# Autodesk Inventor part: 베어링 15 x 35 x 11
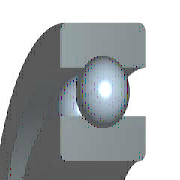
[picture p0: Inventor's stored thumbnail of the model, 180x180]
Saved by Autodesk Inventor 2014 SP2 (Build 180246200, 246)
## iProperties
Created: 2012-02
Part Number: 베어링 15 x 35 x 11
Material: 강철, 연강
Description: 깊은 그루브 볼 베어링
Document SubType Name: Modeling
Standard: KS B 2023
Designer: mduedu
Standards Organization: KS
Language: ko-KR
Size Designation: 6202 - 15 x 35 x 11
Categories: <MemberInstance><Categories><Category DisplayName="샤프트 부품" InternalName="7f7aeb1f-a693-4053-b835-cee3144e0d98" Mnemonic="SHFT"><Category DisplayName="베어링" Inter
Density: 1 g/cm^3
Appearance: 강철
IsCustomPart: 1
Author: mduedu
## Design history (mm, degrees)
sketch "스케치" dims "d0" = 5.2 (= -0.26 x WD + 0.26 x BD)
  geometry: L1 (2.9, 12.5)-(8.1, 12.5); L2 (5.5, 12.5)-(5.5, 9.9); L3 (5.5, 12.5)-(5.5, 15.1); L4 (3.568, 10.76)-(0, 10.76); L5 (0, 7.5)-(11, 7.5); L6 (3.568, 14.24)-(0, 14.24); L7 (0, 17.5)-(11, 17.5); L8 (11, 7.5)-(11, 10.76); L9 (7.432, 10.76)-(11, 10.76); L10 (7.432, 14.24)-(11, 14.24); L11 (11, 17.5)-(11, 14.24); L12 (-1.4, 0)-(8.4, 0) reference; L13 (0, -0.3)-(0, 5.3) reference
  constraints: 22 end point, 4 point on line, 2 collinear, 2 perpendicular, 2 symmetric about line, 1 midpoint, 1 parallel, 14 other
  dimensions: "d9" = 15 diameter of L5 L12 (= WD); "d11" = 35 diameter of L7 L12 (= BD); "d12" = 11 distance between parallel lines of L8 L13 (= KB); "d13" = 21.52 diameter of L9 L12 (= 0.326 x BD + 0.674 x WD)
revolve "본체" stored, may be unused: angle "d6" = 90 deg
revolve "볼" stored, may be unused: angle "d7" = 90 deg
pattern_circular "IDS_ARRAYBALL[SIMPL:T]" dims angle "d3" = 360 deg
body "Solid1"
fillet "모깎기1" dims "d1" = 0.6 (= KRS)
other parameters: "WD" = 15 [user parameter; used in 5 equation terms], "BD" = 35 [user parameter; used in 5 equation terms], "KB" = 11 [user parameter; used in 1 equation term], "KRS" = 0.6 [user parameter; used in 1 equation term], "d4" = 0, "d5" = 0, "d8" = 0, "d14" = 0, "d15" = 0, "BBA" = 0 [user parameter], "BC0" = 3750000 [user parameter], "BC" = 7800000 [user parameter], "BR" = 17.5 (= 0.5 x BD) [user parameter], "WR" = 7.5 (= 0.5 x WD) [user parameter]
